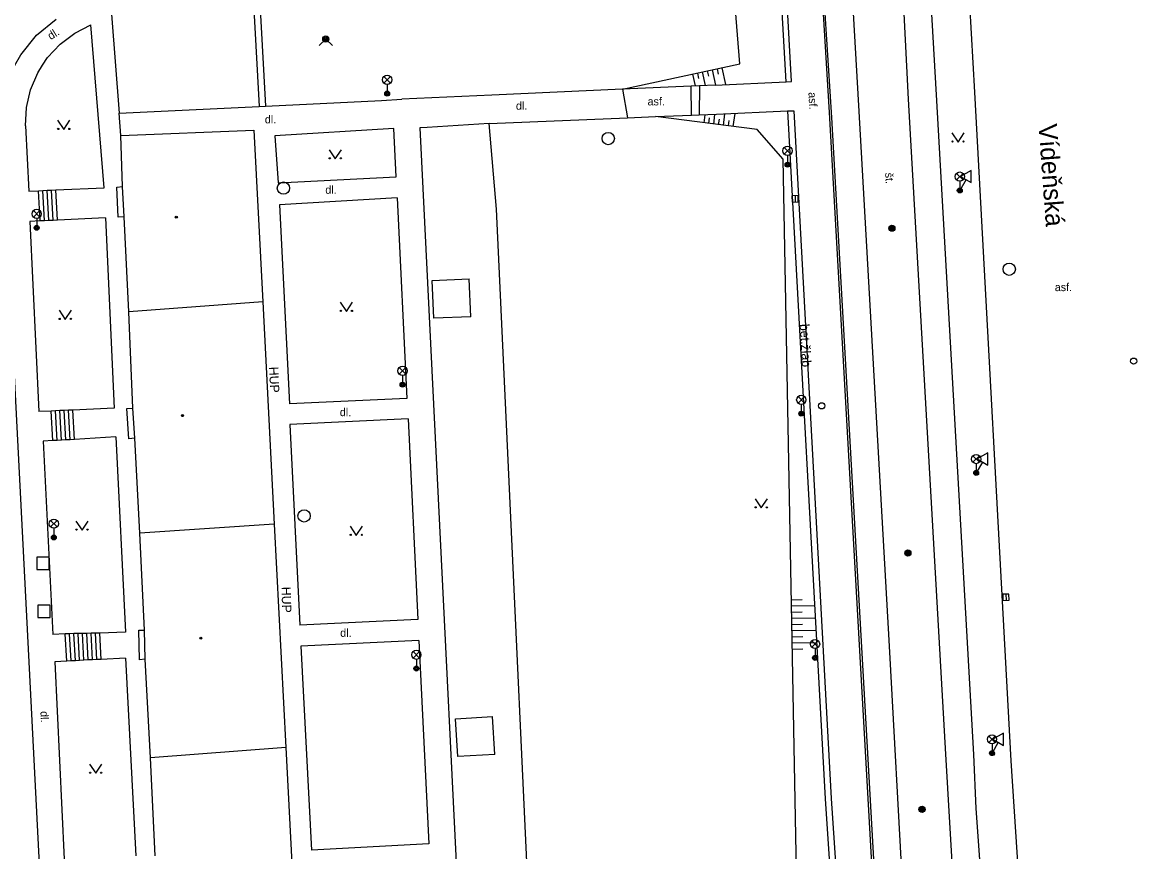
# Model space of a CAD drawing. Extents: x -599951 to -598963, y -1164095 to -1162939.
# Drawn here: x -599318.9 to -599228.4, y -1163072.6 to -1163005.2 of the extents above; entities that cross this region are included whole.
import ezdxf

# ---------------------------------------------------------------- set-up
doc = ezdxf.new("R2010")
doc.units = 0
for name, color, linetype in [('Level 10', 7, 'Continuous'), ('Level 11', 7, 'Continuous'), ('Level 13', 7, 'Continuous'), ('Level 14', 7, 'Continuous'), ('Level 15', 7, 'Continuous'), ('Level 25', 7, 'Continuous'), ('Level 26', 7, 'Continuous'), ('Level 27', 7, 'Continuous'), ('Level 28', 7, 'Continuous'), ('Level 31', 7, 'Continuous'), ('Level 33', 7, 'Continuous'), ('Level 34', 7, 'Continuous'), ('Level 36', 7, 'Continuous'), ('Level 39', 7, 'Continuous'), ('Level 40', 7, 'Continuous'), ('Level 41', 7, 'Continuous'), ('Level 42', 7, 'Continuous'), ('Level 49', 7, 'Continuous'), ('Level 5', 7, 'Continuous'), ('Level 7', 7, 'Continuous'), ('Level 9', 7, 'Continuous')]:
    doc.layers.add(name, color=color, linetype=linetype)

msp = doc.modelspace()

# ---------------------------------------------------------------- linework, layer by layer
at = {"layer": 'Level 10'}
for points in [[(-599235.1, -1163108.54), (-599236.69, -1163094.1), (-599238.6, -1163065.25), (-599241.55, -1163010.92), (-599245.616, -1162939.4)], [(-599320.58, -1163013.74), (-599320.473, -1163011.695), (-599319.945, -1163009.717), (-599319.53, -1163008.78), (-599319.019, -1163007.891), (-599317.736, -1163006.295), (-599316.15, -1163005)], [(-599314.2, -1163139.3), (-599316.54, -1163092.74), (-599319.44, -1163035.48), (-599320.58, -1163013.74)]]:
    msp.add_lwpolyline(points, dxfattribs=at)
at = {"layer": 'Level 11'}
for points in [[(-599256.88, -1163010.08), (-599257.66, -1162996.31), (-599260.31, -1162948.14)], [(-599256.88, -1163010.08), (-599256.44, -1163010.06), (-599257.19, -1162996.28), (-599259.89, -1162948.12)], [(-599300.77, -1162991.86), (-599299.66, -1163012.08)], [(-599300.27, -1162991.84), (-599299.15, -1163012.05)], [(-599237.83, -1163111.49), (-599238.1, -1163108.93), (-599239.62, -1163094.44), (-599241.44, -1163069.14), (-599241.62, -1163064.75), (-599244.67, -1163011.13), (-599245.53, -1162996.1)], [(-599311.66, -1163004.58), (-599311.03, -1163012.64)], [(-599246.78, -1163110.11), (-599248.77, -1163090.46), (-599253.16, -1163012.98), (-599253.71, -1163004.52)], [(-599318.65, -1163013.66), (-599318.569, -1163012.177), (-599318.232, -1163010.73), (-599317.65, -1163009.364), (-599317.27, -1163008.72), (-599316.84, -1163008.118), (-599315.828, -1163007.032), (-599314.642, -1163006.137), (-599313.32, -1163005.46)], [(-599316.17, -1163018.87), (-599312.24, -1163018.7), (-599313.32, -1163005.46)], [(-599270.17, -1163010.69), (-599280.76, -1163011.16), (-599288.07, -1163011.5)], [(-599270.17, -1163010.69), (-599269.74, -1163013)], [(-599270.17, -1163010.69), (-599270.16, -1163010.69)], [(-599264.58, -1163010.44), (-599270.16, -1163010.69)], [(-599263.9, -1163010.41), (-599264.58, -1163010.44)], [(-599264.56, -1163012.8), (-599264.58, -1163010.44)], [(-599263.9, -1163010.41), (-599263.92, -1163012.77)], [(-599262.64, -1163010.35), (-599263.9, -1163010.41)], [(-599262.64, -1163010.35), (-599256.88, -1163010.08)], [(-599311.03, -1163012.64), (-599299.66, -1163012.08), (-599299.15, -1163012.05), (-599289.74, -1163011.59), (-599288.07, -1163011.5)], [(-599262.52, -1163012.72), (-599256.75, -1163012.45)], [(-599256.75, -1163012.45), (-599256.25, -1163012.43), (-599253.2, -1163068.32), (-599251.46, -1163094.33), (-599249.79, -1163110.51)], [(-599256.75, -1163012.45), (-599253.7, -1163068.35), (-599251.96, -1163094.37), (-599250.29, -1163110.58)], [(-599310.89, -1163014.45), (-599311.03, -1163012.64)], [(-599280.98, -1163013.46), (-599286.03, -1163013.8)], [(-599280.98, -1163013.46), (-599269.74, -1163013)], [(-599269.74, -1163013), (-599267.49, -1163012.91)], [(-599267.49, -1163012.91), (-599264.56, -1163012.8)], [(-599264.56, -1163012.8), (-599263.92, -1163012.77)], [(-599263.92, -1163012.77), (-599262.52, -1163012.72)], [(-599318.65, -1163013.66), (-599318.37, -1163018.96)], [(-599288.73, -1163013.88), (-599298.38, -1163014.47), (-599298.13, -1163018.29), (-599288.54, -1163017.81), (-599288.73, -1163013.88)], [(-599286.03, -1163013.8), (-599286.62, -1163013.83), (-599281.92, -1163108.55)], [(-599317.22, -1163018.92), (-599316.87, -1163018.9)], [(-599316.87, -1163018.9), (-599316.52, -1163018.89)], [(-599316.75, -1163021.36), (-599316.87, -1163018.9)], [(-599316.52, -1163018.89), (-599316.17, -1163018.87)], [(-599316.4, -1163021.34), (-599316.52, -1163018.89)], [(-599316.05, -1163021.32), (-599316.17, -1163018.87)], [(-599310.63, -1163021.06), (-599311.1, -1163021.08), (-599311.23, -1163018.63), (-599310.76, -1163018.6)], [(-599318.37, -1163018.96), (-599317.57, -1163018.93)], [(-599317.57, -1163018.93), (-599317.22, -1163018.92)], [(-599317.45, -1163021.39), (-599317.57, -1163018.93)], [(-599317.1, -1163021.37), (-599317.22, -1163018.92)], [(-599288.45, -1163019.5), (-599298.02, -1163020.08), (-599297.2, -1163036.25)], [(-599288.45, -1163019.5), (-599287.66, -1163035.81)], [(-599317.45, -1163021.39), (-599318.29, -1163021.43), (-599317.55, -1163036.88)], [(-599317.1, -1163021.37), (-599317.45, -1163021.39)], [(-599316.75, -1163021.36), (-599317.1, -1163021.37)], [(-599316.4, -1163021.34), (-599316.75, -1163021.36)], [(-599316.05, -1163021.32), (-599316.4, -1163021.34)], [(-599312.14, -1163021.13), (-599316.05, -1163021.32)], [(-599312.14, -1163021.13), (-599311.45, -1163036.61)], [(-599285.49, -1163029.3), (-599285.62, -1163026.23), (-599282.61, -1163026.1)], [(-599282.48, -1163029.17), (-599282.61, -1163026.1)], [(-599282.48, -1163029.17), (-599285.49, -1163029.3)], [(-599287.66, -1163035.81), (-599297.2, -1163036.25)], [(-599316.55, -1163036.83), (-599317.55, -1163036.88)], [(-599316.2, -1163036.82), (-599316.55, -1163036.83)], [(-599316.41, -1163039.24), (-599316.55, -1163036.83)], [(-599315.85, -1163036.8), (-599316.2, -1163036.82)], [(-599316.06, -1163039.22), (-599316.2, -1163036.82)], [(-599315.5, -1163036.79), (-599315.85, -1163036.8)], [(-599315.71, -1163039.2), (-599315.85, -1163036.8)], [(-599315.15, -1163036.77), (-599315.5, -1163036.79)], [(-599315.36, -1163039.18), (-599315.5, -1163036.79)], [(-599314.8, -1163036.76), (-599315.15, -1163036.77)], [(-599315.02, -1163039.16), (-599315.15, -1163036.77)], [(-599311.45, -1163036.61), (-599314.8, -1163036.76)], [(-599314.67, -1163039.14), (-599314.8, -1163036.76)], [(-599309.76, -1163039.05), (-599310.26, -1163039.08), (-599310.41, -1163036.62), (-599309.91, -1163036.59)], [(-599287.57, -1163037.46), (-599297.17, -1163037.94)], [(-599287.57, -1163037.46), (-599286.77, -1163053.77)], [(-599297.17, -1163037.94), (-599296.37, -1163054.24)], [(-599316.41, -1163039.24), (-599317.2, -1163039.29)], [(-599317.2, -1163039.29), (-599316.41, -1163054.99)], [(-599316.06, -1163039.22), (-599316.41, -1163039.24)], [(-599315.71, -1163039.2), (-599316.06, -1163039.22)], [(-599315.36, -1163039.18), (-599315.71, -1163039.2)], [(-599315.02, -1163039.16), (-599315.36, -1163039.18)], [(-599314.67, -1163039.14), (-599315.02, -1163039.16)], [(-599311.31, -1163038.93), (-599314.67, -1163039.14)], [(-599311.31, -1163038.93), (-599310.53, -1163054.81)], [(-599286.77, -1163053.77), (-599296.37, -1163054.24)], [(-599315.41, -1163054.94), (-599316.41, -1163054.99)], [(-599315.06, -1163054.93), (-599315.41, -1163054.94)], [(-599315.29, -1163057.16), (-599315.41, -1163054.94)], [(-599314.71, -1163054.92), (-599315.06, -1163054.93)], [(-599314.94, -1163057.14), (-599315.06, -1163054.93)], [(-599314.36, -1163054.91), (-599314.71, -1163054.92)], [(-599314.59, -1163057.12), (-599314.71, -1163054.92)], [(-599314.01, -1163054.9), (-599314.36, -1163054.91)], [(-599314.24, -1163057.1), (-599314.36, -1163054.91)], [(-599313.89, -1163057.08), (-599314.01, -1163054.9)], [(-599313.66, -1163054.9), (-599314.01, -1163054.9)], [(-599313.31, -1163054.89), (-599313.66, -1163054.9)], [(-599313.54, -1163057.06), (-599313.66, -1163054.9)], [(-599313.19, -1163057.04), (-599313.31, -1163054.89)], [(-599312.96, -1163054.89), (-599313.31, -1163054.89)], [(-599312.61, -1163054.88), (-599312.96, -1163054.89)], [(-599312.84, -1163057.02), (-599312.96, -1163054.89)], [(-599310.53, -1163054.81), (-599312.61, -1163054.88)], [(-599312.5, -1163057.01), (-599312.61, -1163054.88)], [(-599308.91, -1163056.99), (-599309.37, -1163057.06), (-599309.44, -1163054.65), (-599308.98, -1163054.64)], [(-599286.69, -1163055.49), (-599296.29, -1163055.94)], [(-599296.29, -1163055.94), (-599295.41, -1163072.51)], [(-599286.69, -1163055.49), (-599285.88, -1163072)], [(-599310.52, -1163056.9), (-599312.5, -1163057.01)], [(-599310.52, -1163056.9), (-599309.69, -1163072.97)], [(-599315.29, -1163057.16), (-599316.25, -1163057.21)], [(-599316.25, -1163057.21), (-599315.49, -1163073.25)], [(-599314.94, -1163057.14), (-599315.29, -1163057.16)], [(-599314.59, -1163057.12), (-599314.94, -1163057.14)], [(-599314.24, -1163057.1), (-599314.59, -1163057.12)], [(-599313.89, -1163057.08), (-599314.24, -1163057.1)], [(-599313.54, -1163057.06), (-599313.89, -1163057.08)], [(-599313.19, -1163057.04), (-599313.54, -1163057.06)], [(-599312.84, -1163057.02), (-599313.19, -1163057.04)], [(-599312.5, -1163057.01), (-599312.84, -1163057.02)], [(-599283.54, -1163064.91), (-599283.72, -1163061.84), (-599280.71, -1163061.66)], [(-599280.53, -1163064.73), (-599280.71, -1163061.66)], [(-599280.53, -1163064.73), (-599283.54, -1163064.91)], [(-599285.88, -1163072), (-599295.41, -1163072.51)]]:
    msp.add_lwpolyline(points, dxfattribs=at)
at = {"layer": 'Level 13'}
for points in [[(-599251.92, -1162996.02), (-599251, -1163012.01), (-599248.49, -1163055.94), (-599247.39, -1163076.21), (-599246.85, -1163083.41), (-599245.99, -1163094.91), (-599244.38, -1163111.71)], [(-599240.22, -1163111.12), (-599241.9, -1163094.73), (-599243.24, -1163075.81), (-599243.89, -1163064.72), (-599246.94, -1163011.48), (-599247.68, -1162996.45)]]:
    msp.add_lwpolyline(points, dxfattribs=at)
at = {"layer": 'Level 14'}
for points in [[(-599270.16, -1163010.69), (-599260.63, -1163008.63), (-599261.31, -1163000.18)], [(-599251.93, -1163112.47), (-599252.17, -1163110.83), (-599255.8, -1163085.82), (-599257.1, -1163016.36), (-599259.21, -1163013.97), (-599267.49, -1163012.91)]]:
    msp.add_lwpolyline(points, dxfattribs=at)
at = {"layer": 'Level 15'}
for points in [[(-599262.09, -1163008.95), (-599261.8, -1163010.31)], [(-599264.23, -1163010.42), (-599264.44, -1163009.45)], [(-599263.95, -1163009.8), (-599264.05, -1163009.37)], [(-599263.42, -1163010.39), (-599263.66, -1163009.28)], [(-599263.27, -1163009.2), (-599263.17, -1163009.63)], [(-599262.88, -1163009.12), (-599262.61, -1163010.35)], [(-599262.48, -1163009.03), (-599262.39, -1163009.46)], [(-599263.46, -1163012.76), (-599263.54, -1163013.42)], [(-599263.15, -1163013.47), (-599263.09, -1163013.01)], [(-599262.75, -1163013.52), (-599262.65, -1163012.73)], [(-599262.35, -1163013.57), (-599262.29, -1163013.12)], [(-599261.95, -1163013.62), (-599261.84, -1163012.69)], [(-599261.56, -1163013.67), (-599261.5, -1163013.22)], [(-599261.16, -1163013.72), (-599261.02, -1163012.65)], [(-599255.58, -1163052.18), (-599256.43, -1163052.2)], [(-599254.55, -1163052.66), (-599256.42, -1163052.7)], [(-599255.56, -1163053.18), (-599256.41, -1163053.2)], [(-599254.5, -1163053.66), (-599256.4, -1163053.7)], [(-599255.54, -1163054.18), (-599256.39, -1163054.2)], [(-599254.45, -1163054.66), (-599256.38, -1163054.7)], [(-599255.52, -1163055.18), (-599256.37, -1163055.2)], [(-599254.39, -1163055.66), (-599256.36, -1163055.7)], [(-599255.5, -1163056.18), (-599256.35, -1163056.2)]]:
    msp.add_lwpolyline(points, dxfattribs=at)
at = {"layer": 'Level 25'}
for centre, radius in [((-599248.28, -1163021.98), 0.25), ((-599248.28, -1163021.98), 0.2), ((-599248.28, -1163021.98), 0.15), ((-599248.28, -1163021.98), 0.1), ((-599248.28, -1163021.98), 0.05), ((-599246.98, -1163048.37), 0.25), ((-599246.98, -1163048.37), 0.2), ((-599246.98, -1163048.37), 0.15), ((-599246.98, -1163048.37), 0.1), ((-599246.98, -1163048.37), 0.05), ((-599245.83, -1163069.2), 0.25), ((-599245.83, -1163069.2), 0.2), ((-599245.83, -1163069.2), 0.15), ((-599245.83, -1163069.2), 0.1), ((-599245.83, -1163069.2), 0.05)]:
    msp.add_circle(centre, radius, dxfattribs=at)
at = {"layer": 'Level 26'}
for points in [[(-599317.72, -1163049.7), (-599316.72, -1163049.7), (-599316.72, -1163048.7), (-599317.72, -1163048.7)], [(-599317.64, -1163053.61), (-599316.64, -1163053.61), (-599316.64, -1163052.61), (-599317.64, -1163052.61)]]:
    msp.add_lwpolyline(points, close=True, dxfattribs=at)
at = {"layer": 'Level 27'}
for p, q in [((-599256.149, -1163019.34), (-599256.131, -1163019.84)), ((-599239.029, -1163051.71), (-599239.011, -1163052.21))]:
    msp.add_line(p, q, dxfattribs=at)
for points in [[(-599256.399, -1163019.349), (-599256.381, -1163019.849), (-599255.881, -1163019.831), (-599255.899, -1163019.331)], [(-599239.279, -1163051.719), (-599239.261, -1163052.219), (-599238.761, -1163052.201), (-599238.779, -1163051.701)]]:
    msp.add_lwpolyline(points, close=True, dxfattribs=at)
for centre in [(-599271.31, -1163014.69), (-599297.69, -1163018.72), (-599238.75, -1163025.31), (-599296.01, -1163045.36)]:
    msp.add_circle(centre, 0.5, dxfattribs=at)
at = {"layer": 'Level 28'}
for centre in [(-599228.65, -1163032.78), (-599253.99, -1163036.41)]:
    msp.add_circle(centre, 0.25, dxfattribs=at)
at = {"layer": 'Level 31'}
msp.add_lwpolyline([(-599294.78, -1163007.14), (-599294.25, -1163006.61), (-599293.72, -1163007.14)], dxfattribs=at)
for radius in [0.25, 0.18, 0.11]:
    msp.add_circle((-599294.25, -1163006.61), radius, dxfattribs=at)
at = {"layer": 'Level 33'}
for p, q in [((-599289.535, -1163010.18), (-599289.005, -1163009.65)), ((-599289.535, -1163009.65), (-599289.005, -1163010.18)), ((-599289.27, -1163010.29), (-599289.27, -1163011.04)), ((-599257.025, -1163015.95), (-599256.495, -1163015.42)), ((-599257.025, -1163015.42), (-599256.495, -1163015.95)), ((-599256.76, -1163016.06), (-599256.76, -1163016.81)), ((-599243.035, -1163018.05), (-599242.505, -1163017.52)), ((-599243.035, -1163017.52), (-599242.505, -1163018.05)), ((-599242.77, -1163018.16), (-599242.77, -1163018.91)), ((-599317.995, -1163021.08), (-599317.465, -1163020.55)), ((-599317.995, -1163020.55), (-599317.465, -1163021.08)), ((-599317.73, -1163021.19), (-599317.73, -1163021.94)), ((-599288.285, -1163033.83), (-599287.755, -1163033.3)), ((-599288.285, -1163033.3), (-599287.755, -1163033.83)), ((-599288.02, -1163033.94), (-599288.02, -1163034.69)), ((-599255.905, -1163036.19), (-599255.375, -1163035.66)), ((-599255.905, -1163035.66), (-599255.375, -1163036.19)), ((-599255.64, -1163036.3), (-599255.64, -1163037.05)), ((-599241.705, -1163041), (-599241.175, -1163040.47)), ((-599241.705, -1163040.47), (-599241.175, -1163041)), ((-599241.44, -1163041.11), (-599241.44, -1163041.86)), ((-599316.605, -1163046.25), (-599316.075, -1163045.72)), ((-599316.605, -1163045.72), (-599316.075, -1163046.25)), ((-599316.34, -1163046.36), (-599316.34, -1163047.11)), ((-599254.785, -1163056.03), (-599254.255, -1163055.5)), ((-599254.785, -1163055.5), (-599254.255, -1163056.03)), ((-599287.165, -1163056.9), (-599286.635, -1163056.37)), ((-599287.165, -1163056.37), (-599286.635, -1163056.9)), ((-599254.52, -1163056.14), (-599254.52, -1163056.89)), ((-599286.9, -1163057.01), (-599286.9, -1163057.76)), ((-599240.415, -1163063.77), (-599239.885, -1163063.24)), ((-599240.415, -1163063.24), (-599239.885, -1163063.77)), ((-599240.15, -1163063.88), (-599240.15, -1163064.63))]:
    msp.add_line(p, q, dxfattribs=at)
for centre, radius in [((-599289.27, -1163009.915), 0.375), ((-599289.27, -1163011.04), 0.2), ((-599289.27, -1163011.04), 0.145), ((-599289.27, -1163011.04), 0.0876), ((-599256.76, -1163015.685), 0.375), ((-599256.76, -1163016.81), 0.2), ((-599256.76, -1163016.81), 0.145), ((-599256.76, -1163016.81), 0.0876), ((-599242.77, -1163017.785), 0.375), ((-599242.77, -1163018.91), 0.2), ((-599242.77, -1163018.91), 0.145), ((-599242.77, -1163018.91), 0.0876), ((-599317.73, -1163020.815), 0.375), ((-599317.73, -1163021.94), 0.2), ((-599317.73, -1163021.94), 0.145), ((-599317.73, -1163021.94), 0.0876), ((-599288.02, -1163033.565), 0.375), ((-599288.02, -1163034.69), 0.2), ((-599288.02, -1163034.69), 0.145), ((-599288.02, -1163034.69), 0.0876), ((-599255.64, -1163035.925), 0.375), ((-599255.64, -1163037.05), 0.2), ((-599255.64, -1163037.05), 0.145), ((-599255.64, -1163037.05), 0.0876), ((-599241.44, -1163040.735), 0.375), ((-599241.44, -1163041.86), 0.2), ((-599241.44, -1163041.86), 0.145), ((-599241.44, -1163041.86), 0.0876), ((-599316.34, -1163045.985), 0.375), ((-599316.34, -1163047.11), 0.2), ((-599316.34, -1163047.11), 0.145), ((-599316.34, -1163047.11), 0.0876), ((-599254.52, -1163055.765), 0.375), ((-599286.9, -1163056.635), 0.375), ((-599254.52, -1163056.89), 0.2), ((-599254.52, -1163056.89), 0.145), ((-599254.52, -1163056.89), 0.0876), ((-599286.9, -1163057.76), 0.2), ((-599286.9, -1163057.76), 0.145), ((-599286.9, -1163057.76), 0.0876), ((-599240.15, -1163063.505), 0.375), ((-599240.15, -1163064.63), 0.2), ((-599240.15, -1163064.63), 0.145), ((-599240.15, -1163064.63), 0.0876)]:
    msp.add_circle(centre, radius, dxfattribs=at)
at = {"layer": 'Level 34'}
for p, q in [((-599242.987, -1163018.785), (-599242.553, -1163019.034)), ((-599242.263, -1163018.027), (-599242.77, -1163018.91)), ((-599240.933, -1163040.977), (-599241.44, -1163041.86)), ((-599241.657, -1163041.736), (-599241.223, -1163041.984)), ((-599239.643, -1163063.747), (-599240.15, -1163064.63)), ((-599240.367, -1163064.506), (-599239.933, -1163064.754))]:
    msp.add_line(p, q, dxfattribs=at)
for points in [[(-599242.697, -1163017.778), (-599241.83, -1163018.276), (-599241.832, -1163017.276)], [(-599241.367, -1163040.728), (-599240.5, -1163041.226), (-599240.502, -1163040.226)], [(-599240.077, -1163063.498), (-599239.21, -1163063.996), (-599239.212, -1163062.996)]]:
    msp.add_lwpolyline(points, close=True, dxfattribs=at)
at = {"layer": 'Level 36'}
for points in [[(-599316.03, -1163013.21), (-599315.53, -1163013.96), (-599315.03, -1163013.21)], [(-599243.41, -1163014.23), (-599242.91, -1163014.98), (-599242.41, -1163014.23)], [(-599293.98, -1163015.6), (-599293.48, -1163016.35), (-599292.98, -1163015.6)], [(-599315.91, -1163028.65), (-599315.41, -1163029.4), (-599314.91, -1163028.65)], [(-599293.08, -1163028), (-599292.58, -1163028.75), (-599292.08, -1163028)], [(-599259.39, -1163043.96), (-599258.89, -1163044.71), (-599258.39, -1163043.96)], [(-599314.55, -1163045.77), (-599314.05, -1163046.52), (-599313.55, -1163045.77)], [(-599292.28, -1163046.19), (-599291.78, -1163046.94), (-599291.28, -1163046.19)], [(-599313.44, -1163065.52), (-599312.94, -1163066.27), (-599312.44, -1163065.52)]]:
    msp.add_lwpolyline(points, dxfattribs=at)
for centre in [(-599315.98, -1163013.91), (-599315.081, -1163013.91), (-599243.36, -1163014.93), (-599242.461, -1163014.93), (-599293.93, -1163016.3), (-599293.031, -1163016.3), (-599293.03, -1163028.7), (-599292.131, -1163028.7), (-599315.86, -1163029.35), (-599314.961, -1163029.35), (-599259.34, -1163044.66), (-599258.441, -1163044.66), (-599314.5, -1163046.47), (-599313.601, -1163046.47), (-599292.23, -1163046.89), (-599291.331, -1163046.89), (-599313.39, -1163066.22), (-599312.491, -1163066.22)]:
    msp.add_circle(centre, 0.05, dxfattribs=at)
at = {"layer": 'Level 39'}
for centre, radius in [((-599306.39, -1163021.08), 0.09), ((-599306.39, -1163021.08), 0.0398), ((-599305.89, -1163037.2), 0.09), ((-599305.89, -1163037.2), 0.0398), ((-599304.4, -1163055.29), 0.09), ((-599304.4, -1163055.29), 0.0398)]:
    msp.add_circle(centre, radius, dxfattribs=at)
at = {"layer": 'Level 5'}
for points in [[(-599310.89, -1163014.45), (-599300.09, -1163014.01)], [(-599300.09, -1163014.01), (-599299.37, -1163027.96)], [(-599310.76, -1163018.6), (-599310.89, -1163014.45)], [(-599310.63, -1163021.06), (-599310.76, -1163018.6)], [(-599310.26, -1163028.76), (-599310.63, -1163021.06)], [(-599299.37, -1163027.96), (-599310.26, -1163028.76)], [(-599299.37, -1163027.96), (-599298.44, -1163046.02)], [(-599309.91, -1163036.59), (-599310.26, -1163028.76)], [(-599309.76, -1163039.05), (-599309.91, -1163036.59)], [(-599309.36, -1163046.75), (-599309.76, -1163039.05)], [(-599298.44, -1163046.02), (-599309.36, -1163046.75)], [(-599298.44, -1163046.02), (-599297.51, -1163064.17)], [(-599308.98, -1163054.64), (-599309.36, -1163046.75)], [(-599308.91, -1163056.99), (-599308.98, -1163054.64)], [(-599308.48, -1163065.01), (-599308.91, -1163056.99)], [(-599297.51, -1163064.17), (-599308.48, -1163065.01)], [(-599308.1, -1163072.97), (-599308.48, -1163065.01)], [(-599297.51, -1163064.17), (-599296.55, -1163082.45)]]:
    msp.add_lwpolyline(points, dxfattribs=at)
at = {"layer": 'Level 7'}
for points in [[(-599280.39, -1163020.42), (-599280.98, -1163013.46)], [(-599275.53, -1163118.45), (-599276.68, -1163100.28), (-599280.39, -1163020.42)]]:
    msp.add_lwpolyline(points, dxfattribs=at)
at = {"layer": 'Level 9'}
msp.add_lwpolyline([(-599254.3, -1162997.42), (-599253.37, -1163012.58), (-599249.04, -1163089.47), (-599246.77, -1163112.49), (-599245.51, -1163121.3), (-599244.18, -1163129.29)], dxfattribs=at)

# ---------------------------------------------------------------- texts
at = {"layer": 'Level 40'}
for s, rotation, p in [('dl.', 31.81, (-599316.59, -1163006.7)), ('asf.', 273, (-599255.06, -1163010.94)), ('št.', 273, (-599248.83, -1163017.48)), ('dl.', 272.72, (-599317.43, -1163061.23))]:
    msp.add_text(s, height=0.65, rotation=rotation, dxfattribs=at).set_placement(p)
for s, p in [('dl.', (-599278.81, -1163012.35)), ('asf.', (-599268.12, -1163012)), ('dl.', (-599299.2, -1163013.46)), ('dl.', (-599294.29, -1163019.18)), ('asf.', (-599235.05, -1163027.09)), ('dl.', (-599293.11, -1163037.25)), ('dl.', (-599293.08, -1163055.18))]:
    msp.add_text(s, height=0.65, dxfattribs=at).set_placement(p)
at = {"layer": 'Level 41'}
for rotation, p in [(272.83, (-599298.87, -1163033.25)), (271.55, (-599297.85, -1163051.12))]:
    msp.add_text('HUP', height=0.75, rotation=rotation, dxfattribs=at).set_placement(p)
at = {"layer": 'Level 42'}
msp.add_text('bet.žlab', height=0.75, rotation=273.12362, dxfattribs=at).set_placement((-599255.76, -1163029.77))
at = {"layer": 'Level 49'}
msp.add_text('Vídeňská', height=1.5, rotation=274.2, dxfattribs=at).set_placement((-599236.38, -1163013.55))

doc.saveas('drawing.dxf')
